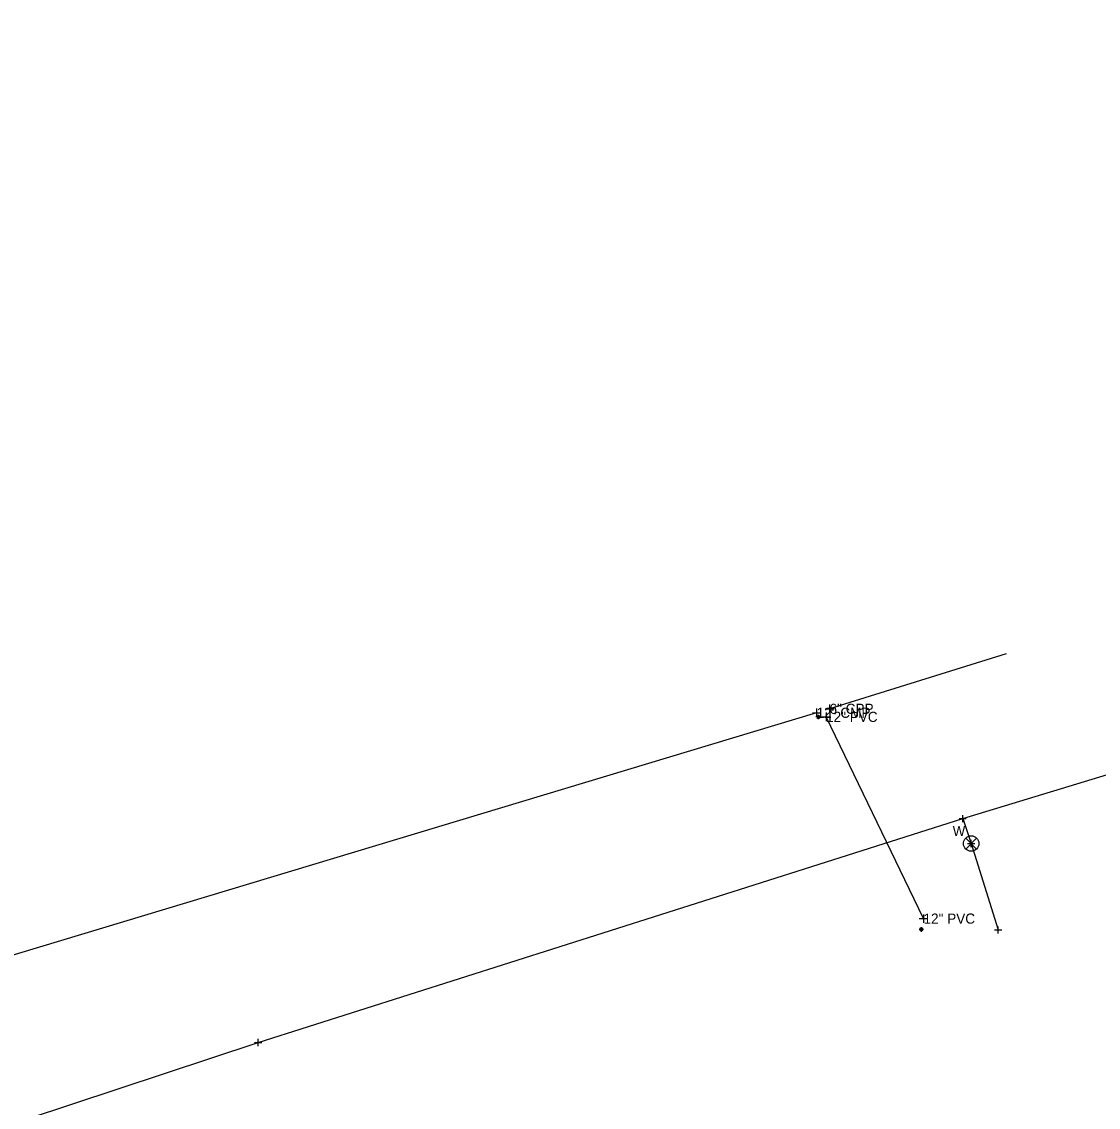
# Model space of a CAD drawing. Extents: x 1729655 to 1739338, y 463812 to 469501.
# Drawn here: x 1735905.4 to 1736096.3, y 467112.2 to 467304.7 of the extents above; entities that cross this region are included whole.
import ezdxf

# ---------------------------------------------------------------- set-up
doc = ezdxf.new("R2010")
doc.units = 0
for name, color, linetype in [('S_Bridge_Column_Round', 7, 'Continuous'), ('S_Bridge_ExpansionJoint', 7, 'Continuous'), ('S_Drainage_Sump', 7, 'Continuous'), ('S_Ground_LevelString', 7, 'Continuous'), ('S_RetWall_Top', 7, 'Continuous'), ('S_Survey_Shot', 7, 'Continuous'), ('S_Terrain_High_Points', 7, 'Continuous')]:
    doc.layers.add(name, color=color, linetype=linetype)

msp = doc.modelspace()

# ---------------------------------------------------------------- linework, layer by layer
at = {"layer": 'S_Bridge_Column_Round'}
for p, q in [((1736071.61, 467163.39), (1736072.88, 467163.4)), ((1736071.61, 467163.39), (1736072.88, 467163.4)), ((1736072.25, 467162.76), (1736072.24, 467164.03)), ((1736072.25, 467162.76), (1736072.24, 467164.03)), ((1736072.24, 467163.39), (1736072.24, 467163.39)), ((1736072.24, 467163.39), (1736072.24, 467163.39)), ((1736073.75, 467158.34), (1736073.75, 467159.61)), ((1736073.11, 467158.97), (1736074.38, 467158.97)), ((1736073.75, 467158.97), (1736073.75, 467158.97)), ((1736078.53, 467143), (1736078.53, 467144.27)), ((1736077.89, 467143.64), (1736079.17, 467143.64)), ((1736078.53, 467143.64), (1736078.53, 467143.64)), ((1735946.67, 467123.71), (1735947.95, 467123.71)), ((1735947.31, 467123.07), (1735947.31, 467124.34)), ((1735947.31, 467123.71), (1735947.31, 467123.71))]:
    msp.add_line(p, q, dxfattribs=at)
at = {"layer": 'S_Bridge_ExpansionJoint'}
for p, q in [((1736045.59, 467182.16), (1736047.09, 467182.16)), ((1736046.34, 467182.91), (1736046.34, 467181.41)), ((1736047.88, 467182.86), (1736049.38, 467182.86)), ((1736048.01, 467182.18), (1736048.01, 467180.68)), ((1736048.63, 467183.61), (1736048.63, 467182.11)), ((1736047.26, 467181.43), (1736048.76, 467181.43)), ((1736064.54, 467145.66), (1736066.04, 467145.66)), ((1736065.29, 467146.41), (1736065.29, 467144.91))]:
    msp.add_line(p, q, dxfattribs=at)
at = {"layer": 'S_Drainage_Sump'}
for p, q in [((1736047.01, 467181.42), (1736046.22, 467181.42)), ((1736046.88, 467181.16), (1736046.35, 467181.68)), ((1736046.88, 467181.68), (1736046.35, 467181.16)), ((1736046.61, 467181.82), (1736046.61, 467181.03)), ((1736065.29, 467143.73), (1736064.51, 467143.73)), ((1736065.16, 467143.47), (1736064.64, 467144)), ((1736065.16, 467144), (1736064.64, 467143.47)), ((1736064.9, 467144.13), (1736064.9, 467143.34))]:
    msp.add_line(p, q, dxfattribs=at)
at = {"layer": 'S_Ground_LevelString'}
for p, q in [((1736072.78, 467159.94), (1736074.72, 467158)), ((1736072.78, 467158), (1736074.72, 467159.94))]:
    msp.add_line(p, q, dxfattribs=at)
msp.add_circle((1736073.75, 467158.97), 1.37, dxfattribs=at)
at = {"layer": 'S_RetWall_Top'}
for p, q in [((1736079.94, 467192.59), (1736048.63, 467182.86)), ((1736046.34, 467182.16), (1735892.5, 467135.8)), ((1736065.29, 467145.66), (1736048.01, 467181.43))]:
    msp.add_line(p, q, dxfattribs=at)
at = {"layer": 'S_Survey_Shot'}
for points in [[(1735327.94, 466925.11), (1735706.87, 467043.8), (1735777.22, 467067.85), (1735856.5, 467093.65), (1735947.31, 467123.71), (1736072.24, 467163.39), (1736148.46, 467186.6), (1736188.58, 467199.8), (1736250.41, 467218.61), (1736341.55, 467246.49), (1736425.62, 467273.68), (1736484.8, 467292.24), (1736522.29, 467304.69), (1736527.82, 467289.35)], [(1736072.24, 467163.39), (1736073.75, 467158.97), (1736078.53, 467143.64)]]:
    msp.add_lwpolyline(points, dxfattribs=at)

# ---------------------------------------------------------------- texts
at = {"layer": 'S_Ground_LevelString'}
msp.add_text('W', height=1.75, dxfattribs=at).set_placement((1736070.48, 467160.31))
at = {"layer": 'S_Terrain_High_Points'}
for s, p in [('12" CMP', (1736046.34, 467181.26)), ('12" PVC', (1736048.01, 467180.53)), ('6" CPP', (1736048.63, 467181.96)), ('12" PVC', (1736065.29, 467144.76))]:
    msp.add_text(s, height=1.8, dxfattribs=at).set_placement(p)

doc.saveas('drawing.dxf')
